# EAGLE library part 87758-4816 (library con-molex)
48 Pin - 2mm Dual Row Single Wafer, Vertical T/H HDR Source: http://www.molex.com/pdm_docs/sd/877580616_sd.pdf
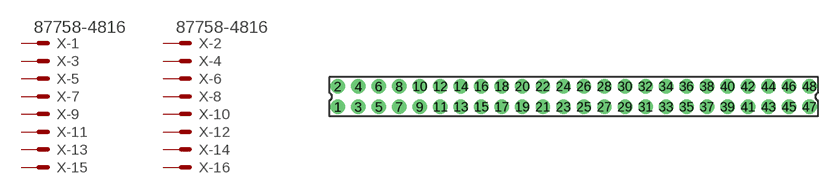
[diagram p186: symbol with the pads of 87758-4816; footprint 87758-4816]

Designator prefix X; gates -1=MV -2=MV -3=M -4=M -5=M -6=M -7=M -8=M -9=M -10=M -11=M -12=M -13=M -14=M -15=M -16=M -17=M -18=M -19=M -20=M -21=M -22=M -23=M -24=M -25=M -26=M -27=M -28=M -29=M -30=M -31=M -32=M -33=M -34=M -35=M -36=M -37=M -38=M -39=M -40=M -41=M -42=M -43=M -44=M -45=M -46=M -47=M -48=M

## 87758-4816 (MPN: 87758-4816; OC_FARNELL: unknown; OC_NEWARK: 25M5696)  [87758-4816]
1  -1:S  pas
2  -2:S  pas
3  -3:S  pas
4  -4:S  pas
5  -5:S  pas
6  -6:S  pas
7  -7:S  pas
8  -8:S  pas
9  -9:S  pas
10  -10:S  pas
11  -11:S  pas
12  -12:S  pas
13  -13:S  pas
14  -14:S  pas
15  -15:S  pas
16  -16:S  pas
17  -17:S  pas
18  -18:S  pas
19  -19:S  pas
20  -20:S  pas
21  -21:S  pas
22  -22:S  pas
23  -23:S  pas
24  -24:S  pas
25  -25:S  pas
26  -26:S  pas
27  -27:S  pas
28  -28:S  pas
29  -29:S  pas
30  -30:S  pas
31  -31:S  pas
32  -32:S  pas
33  -33:S  pas
34  -34:S  pas
35  -35:S  pas
36  -36:S  pas
37  -37:S  pas
38  -38:S  pas
39  -39:S  pas
40  -40:S  pas
41  -41:S  pas
42  -42:S  pas
43  -43:S  pas
44  -44:S  pas
45  -45:S  pas
46  -46:S  pas
47  -47:S  pas
48  -48:S  pas

## Footprint 87758-4816 (pad centres in mm)
48 Pin - 2mm Dual Row Single Wafer, Vertical T/H HDR Source: http://www.molex.com/pdm_docs/sd/877580616_sd.pdf
drill 0.9 pad 1.27 round: 1 -23,-1; 2 -23,1; 3 -21,-1; 4 -21,1; 5 -19,-1; 6 -19,1; 7 -17,-1; 8 -17,1; 9 -15,-1; 10 -15,1; 11 -13,-1; 12 -13,1; 13 -11,-1; 14 -11,1; 15 -9,-1; 16 -9,1; 17 -7,-1; 18 -7,1; 19 -5,-1; 20 -5,1; 21 -3,-1; 22 -3,1; 23 -1,-1; 24 -1,1; 25 1,-1; 26 1,1; 27 3,-1; 28 3,1; 29 5,-1; 30 5,1; 31 7,-1; 32 7,1; 33 9,-1; 34 9,1; 35 11,-1; 36 11,1; 37 13,-1; 38 13,1; 39 15,-1; 40 15,1; 41 17,-1; 42 17,1; 43 19,-1; 44 19,1; 45 21,-1; 46 21,1; 47 23,-1; 48 23,1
